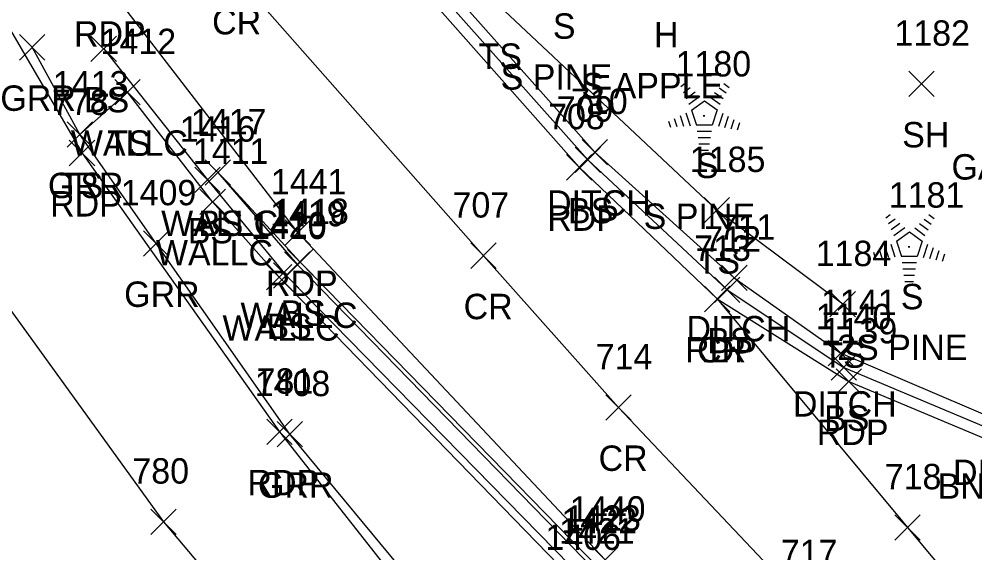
# Model space of a CAD drawing. Extents: x 1647133 to 1649138, y 411736 to 414924.
# Drawn here: x 1648689 to 1648764.3, y 412065.9 to 412107.9 of the extents above; entities that cross this region are included whole.
import ezdxf

# ---------------------------------------------------------------- set-up
doc = ezdxf.new("R2010")
doc.units = 0
for name, color, linetype in [('D_A', 7, 'Continuous'), ('D_I', 7, 'Continuous'), ('D_TIC', 7, 'Continuous'), ('DD', 7, 'Continuous'), ('L_A', 7, 'Continuous'), ('L_C', 7, 'Continuous'), ('L_I', 7, 'Continuous'), ('L_TIC', 7, 'Continuous'), ('LELB', 7, 'Continuous'), ('LTC', 7, 'Continuous'), ('LW', 7, 'Continuous'), ('M_C', 7, 'Continuous'), ('P_A', 7, 'Continuous'), ('P_I', 7, 'Continuous'), ('P_TIC', 7, 'Continuous'), ('PET', 7, 'Continuous'), ('PRC', 7, 'Continuous'), ('R_A', 7, 'Continuous'), ('R_C', 7, 'Continuous'), ('R_I', 7, 'Continuous'), ('R_TIC', 7, 'Continuous'), ('RGR', 7, 'Continuous')]:
    doc.layers.add(name, color=color, linetype=linetype)

msp = doc.modelspace()

# ---------------------------------------------------------------- linework, layer by layer
at = {"layer": 'D_TIC'}
for points in [[(1648733.341, 412096.427), (1648735.341, 412098.427)], [(1648735.341, 412096.427), (1648733.341, 412098.427)], [(1648744.316, 412086.535), (1648746.316, 412088.535)], [(1648746.316, 412086.535), (1648744.316, 412088.535)], [(1648752.692, 412080.611), (1648754.692, 412082.611)], [(1648754.692, 412080.611), (1648752.692, 412082.611)]]:
    msp.add_lwpolyline(points, dxfattribs=at)
at = {"layer": 'DD'}
msp.add_lwpolyline([(1648700.204, 412133.762), (1648700.854, 412134.053), (1648701.48, 412134.614), (1648714.403, 412119.84), (1648734.341, 412097.427), (1648745.316, 412087.535), (1648753.692, 412081.611), (1648766.293, 412076.231), (1648779.329, 412074.391), (1648786.441, 412074.562), (1648790.942, 412077.169), (1648801.739, 412083.078)], dxfattribs=at)
at = {"layer": 'L_TIC'}
for points in [[(1648694.678, 412104.565), (1648696.678, 412106.565)], [(1648696.678, 412104.565), (1648694.678, 412106.565)], [(1648759.039, 412101.804), (1648761.039, 412103.804)], [(1648761.039, 412101.804), (1648759.039, 412103.804)], [(1648696.556, 412101.144), (1648698.556, 412103.144)], [(1648698.556, 412101.144), (1648696.556, 412103.144)], [(1648696.556, 412101.144), (1648698.556, 412103.144)], [(1648698.556, 412101.144), (1648696.556, 412103.144)], [(1648692.801, 412097.81), (1648694.801, 412099.81)], [(1648694.801, 412097.81), (1648692.801, 412099.81)], [(1648732.781, 412095.829), (1648734.781, 412097.829)], [(1648734.781, 412095.829), (1648732.781, 412097.829)], [(1648702.852, 412094.255), (1648704.852, 412096.255)], [(1648704.852, 412094.255), (1648702.852, 412096.255)], [(1648703.664, 412094.833), (1648705.664, 412096.833)], [(1648705.664, 412094.833), (1648703.664, 412096.833)], [(1648703.664, 412094.833), (1648705.664, 412096.833)], [(1648705.664, 412094.833), (1648703.664, 412096.833)], [(1648703.253, 412092.509), (1648705.253, 412094.509)], [(1648705.253, 412092.509), (1648703.253, 412094.509)], [(1648742.94, 412091.867), (1648744.94, 412093.867)], [(1648744.94, 412091.867), (1648742.94, 412093.867)], [(1648709.908, 412087.591), (1648711.908, 412089.591)], [(1648711.908, 412087.591), (1648709.908, 412089.591)], [(1648710.149, 412087.766), (1648712.149, 412089.766)], [(1648712.149, 412087.766), (1648710.149, 412089.766)], [(1648708.494, 412086.59), (1648710.494, 412088.59)], [(1648710.494, 412086.59), (1648708.494, 412088.59)], [(1648709.046, 412086.718), (1648711.046, 412088.718)], [(1648711.046, 412086.718), (1648709.046, 412088.718)], [(1648743.747, 412085.599), (1648745.747, 412087.599)], [(1648745.747, 412085.599), (1648743.747, 412087.599)], [(1648752.845, 412084.455), (1648754.845, 412086.455)], [(1648754.845, 412084.455), (1648752.845, 412086.455)], [(1648752.939, 412079.489), (1648754.939, 412081.489)], [(1648754.939, 412079.489), (1648752.939, 412081.489)]]:
    msp.add_lwpolyline(points, dxfattribs=at)
at = {"layer": 'LELB'}
for points in [[(1648700.854, 412134.053), (1648713.799, 412119.311), (1648733.781, 412096.829), (1648744.747, 412086.599), (1648753.939, 412080.489), (1648766.731, 412075.085), (1648779.502, 412073.38), (1648786.989, 412073.92), (1648803.001, 412081.585)], [(1648753.845, 412085.455), (1648743.94, 412092.867), (1648726.772, 412108.987), (1648717.56, 412121.346)], [(1648695.678, 412105.565), (1648703.852, 412095.255), (1648710.046, 412087.718), (1648733.652, 412063.604), (1648760.182, 412036.756), (1648786.341, 412009.779), (1648811.728, 411984.211), (1648827.527, 411968.324), (1648831.218, 411963.386)], [(1648697.556, 412102.144), (1648693.801, 412098.81)], [(1648704.664, 412095.833), (1648711.149, 412088.766), (1648734.698, 412064.622), (1648761.086, 412037.999), (1648787.653, 412010.792), (1648812.355, 411985.321), (1648827.903, 411969.607)]]:
    msp.add_lwpolyline(points, dxfattribs=at)
at = {"layer": 'LTC'}
for p, q in [((1648741.099, 412102.595), (1648741.453, 412102.853)), ((1648741.308, 412102.13), (1648741.837, 412102.514)), ((1648741.518, 412101.664), (1648742.222, 412102.175)), ((1648743.755, 412102.139), (1648744.434, 412101.645)), ((1648744.126, 412102.487), (1648744.675, 412102.088)), ((1648744.497, 412102.836), (1648744.916, 412102.531)), ((1648741.727, 412101.198), (1648742.606, 412101.836)), ((1648741.952, 412100.743), (1648742.964, 412101.478)), ((1648742.964, 412101.478), (1648743.961, 412100.753)), ((1648743.384, 412101.791), (1648744.193, 412101.202)), ((1648741.952, 412100.743), (1648742.339, 412099.55)), ((1648743.961, 412100.753), (1648743.569, 412099.55)), ((1648740.131, 412099.874), (1648740.283, 412099.407)), ((1648740.587, 412100.091), (1648740.798, 412099.439)), ((1648741.042, 412100.308), (1648741.313, 412099.472)), ((1648741.497, 412100.524), (1648741.828, 412099.505)), ((1648744.398, 412100.482), (1648744.06, 412099.442)), ((1648744.843, 412100.232), (1648744.555, 412099.347)), ((1648745.287, 412099.982), (1648745.05, 412099.252)), ((1648743.569, 412099.55), (1648742.339, 412099.55)), ((1648745.732, 412099.731), (1648745.545, 412099.157)), ((1648743.531, 412099.05), (1648742.387, 412099.05)), ((1648743.447, 412098.55), (1648742.459, 412098.55)), ((1648743.364, 412098.05), (1648742.532, 412098.05)), ((1648743.28, 412097.55), (1648742.605, 412097.55)), ((1648757.229, 412092.27), (1648757.583, 412092.527)), ((1648760.627, 412092.51), (1648761.046, 412092.206)), ((1648757.438, 412091.805), (1648757.968, 412092.189)), ((1648757.648, 412091.339), (1648758.352, 412091.85)), ((1648759.885, 412091.814), (1648760.564, 412091.32)), ((1648760.256, 412092.162), (1648760.806, 412091.763)), ((1648757.858, 412090.873), (1648758.736, 412091.511)), ((1648758.082, 412090.418), (1648759.094, 412091.152)), ((1648759.094, 412091.152), (1648760.091, 412090.428)), ((1648759.514, 412091.465), (1648760.323, 412090.877)), ((1648757.628, 412090.199), (1648757.958, 412089.18)), ((1648758.082, 412090.418), (1648758.469, 412089.225)), ((1648760.091, 412090.428), (1648759.7, 412089.225)), ((1648760.528, 412090.157), (1648760.191, 412089.117)), ((1648756.261, 412089.549), (1648756.413, 412089.081)), ((1648756.717, 412089.766), (1648756.928, 412089.114)), ((1648757.172, 412089.983), (1648757.443, 412089.147)), ((1648760.973, 412089.906), (1648760.686, 412089.022)), ((1648761.418, 412089.656), (1648761.181, 412088.927)), ((1648761.862, 412089.406), (1648761.675, 412088.832)), ((1648759.7, 412089.225), (1648758.469, 412089.225)), ((1648759.661, 412088.725), (1648758.517, 412088.725)), ((1648759.578, 412088.225), (1648758.589, 412088.225)), ((1648759.494, 412087.725), (1648758.662, 412087.725)), ((1648759.41, 412087.225), (1648758.735, 412087.225))]:
    msp.add_line(p, q, dxfattribs=at)
at = {"layer": 'LW'}
for points in [[(1648830.392, 411963.284), (1648792.891, 412001.948), (1648759.271, 412036.695), (1648733.27, 412063.116), (1648709.494, 412087.59), (1648704.253, 412093.509), (1648697.556, 412102.144)], [(1648704.664, 412095.833), (1648710.908, 412088.591), (1648734.403, 412064.434), (1648760.897, 412037.563), (1648787.2, 412010.572), (1648812.273, 411985.189), (1648827.903, 411969.607)]]:
    msp.add_lwpolyline(points, dxfattribs=at)
at = {"layer": 'P_TIC'}
for points in [[(1648692.972, 412096.362), (1648694.972, 412098.362)], [(1648694.972, 412096.362), (1648692.972, 412098.362)], [(1648732.101, 412095.235), (1648734.101, 412097.235)], [(1648734.101, 412095.235), (1648732.101, 412097.235)], [(1648709.962, 412090.103), (1648711.962, 412092.103)], [(1648711.962, 412090.103), (1648709.962, 412092.103)], [(1648724.575, 412088.279), (1648726.575, 412090.279)], [(1648726.575, 412088.279), (1648724.575, 412090.279)], [(1648742.955, 412084.872), (1648744.955, 412086.872)], [(1648744.955, 412084.872), (1648742.955, 412086.872)], [(1648742.955, 412084.872), (1648744.955, 412086.872)], [(1648744.955, 412084.872), (1648742.955, 412086.872)], [(1648753.321, 412078.376), (1648755.321, 412080.376)], [(1648755.321, 412078.376), (1648753.321, 412080.376)], [(1648735.199, 412076.337), (1648737.199, 412078.337)], [(1648737.199, 412076.337), (1648735.199, 412078.337)], [(1648708.507, 412074.411), (1648710.507, 412076.411)], [(1648710.507, 412074.411), (1648708.507, 412076.411)], [(1648699.383, 412067.335), (1648701.383, 412069.335)], [(1648701.383, 412067.335), (1648699.383, 412069.335)], [(1648757.948, 412066.89), (1648759.948, 412068.89)], [(1648759.948, 412066.89), (1648757.948, 412068.89)], [(1648734.153, 412064.343), (1648736.153, 412066.343)], [(1648736.153, 412064.343), (1648734.153, 412066.343)]]:
    msp.add_lwpolyline(points, dxfattribs=at)
at = {"layer": 'PET'}
for points in [[(1648536.119, 412432.998), (1648543.399, 412417.954), (1648546.486, 412415.003), (1648562.248, 412380.849), (1648562.337, 412375.739), (1648565.289, 412369.171), (1648579.297, 412340.19), (1648594.414, 412306.778), (1648606.351, 412280.635), (1648620.629, 412249.259), (1648631.777, 412225.06), (1648641.267, 412204.566), (1648646.814, 412192.55), (1648664.816, 412155.812), (1648677.431, 412126.914), (1648681.854, 412118.139), (1648693.972, 412097.362), (1648709.507, 412075.411), (1648723.887, 412057.125), (1648746.982, 412031.15), (1648768.696, 412011.078), (1648794.521, 411987.621), (1648826.406, 411959.789)], [(1648646.814, 412192.55), (1648654.671, 412182.929), (1648666.114, 412172.04), (1648681.295, 412155.026), (1648700.204, 412133.762), (1648713.219, 412118.744), (1648733.101, 412096.235), (1648743.955, 412085.872), (1648754.321, 412079.376), (1648767.034, 412074.054), (1648779.661, 412072.471), (1648787.719, 412072.973), (1648803.342, 412081.153)], [(1648833.709, 411965.976), (1648813.189, 411986.13), (1648788.104, 412011.597), (1648761.506, 412038.635), (1648735.153, 412065.343), (1648710.962, 412091.103), (1648695.849, 412110.74)]]:
    msp.add_lwpolyline(points, dxfattribs=at)
at = {"layer": 'PRC'}
for points in [[(1648523.855, 412428.164), (1648541.762, 412388.819), (1648560.786, 412347.218), (1648578.952, 412307.656), (1648596.522, 412268.849), (1648615.514, 412228.06), (1648629.383, 412198.525), (1648645.407, 412164.541), (1648659.578, 412134.14), (1648672.041, 412110.748), (1648683.898, 412091.11), (1648700.383, 412068.335), (1648715.839, 412049.98), (1648739.601, 412024.905), (1648761.868, 412004.355), (1648787.636, 411981.064), (1648820.993, 411950.624), (1648837.381, 411936.249), (1648865.129, 411910.894), (1648893.845, 411885.618), (1648930.35, 411852.903), (1648951.421, 411834.103), (1648988.1, 411800.425), (1649025.041, 411766.663)], [(1648664.816, 412155.812), (1648676.979, 412144.697), (1648692.804, 412127.015), (1648705.779, 412111.7), (1648725.575, 412089.279), (1648736.199, 412077.337), (1648750.767, 412061.914), (1648770.244, 412040.325), (1648787.372, 412023.03), (1648802.926, 412006.988), (1648820.913, 411988.588), (1648839.835, 411968.01), (1648856.098, 411949.207), (1648864.815, 411933.931), (1648873.225, 411921.132)], [(1648743.955, 412085.872), (1648758.948, 412067.89), (1648776.375, 412047.027), (1648792.583, 412027.973)]]:
    msp.add_lwpolyline(points, dxfattribs=at)
at = {"layer": 'R_TIC'}
for points in [[(1648689.054, 412104.682), (1648691.054, 412106.682)], [(1648691.054, 412104.682), (1648689.054, 412106.682)], [(1648692.801, 412097.81), (1648694.801, 412099.81)], [(1648694.801, 412097.81), (1648692.801, 412099.81)], [(1648698.799, 412089.248), (1648700.799, 412091.248)], [(1648700.799, 412089.248), (1648698.799, 412091.248)], [(1648709.333, 412074.22), (1648711.333, 412076.22)], [(1648711.333, 412074.22), (1648709.333, 412076.22)]]:
    msp.add_lwpolyline(points, dxfattribs=at)
at = {"layer": 'RGR'}
msp.add_lwpolyline([(1648828.248, 411959.455), (1648783.912, 411998.445), (1648752.672, 412027.834), (1648730.332, 412051.085), (1648710.333, 412075.22), (1648699.799, 412090.248), (1648693.801, 412098.81), (1648690.054, 412105.682)], dxfattribs=at)

# ---------------------------------------------------------------- texts
at = {"layer": 'D_A'}
for p in [(1648730.577, 412092.427), (1648741.552, 412082.535), (1648749.928, 412076.611), (1648762.529, 412071.231)]:
    msp.add_text('DITCH', height=2, dxfattribs=at).set_placement(p)
at = {"layer": 'D_I'}
for s, p in [('710', (1648732.459, 412100.427)), ('711', (1648744.087, 412090.535)), ('1141', (1648752.133, 412084.611))]:
    msp.add_text(s, height=2, dxfattribs=at).set_placement(p)
at = {"layer": 'L_A'}
for s, p in [('S', (1648731.032, 412106.356)), ('H', (1648738.99, 412105.672)), ('TS', (1648725.181, 412103.987)), ('BS', (1648694.119, 412100.565)), ('WALLC', (1648693.091, 412097.144)), ('TS', (1648695.965, 412097.144)), ('SH', (1648758.527, 412097.804)), ('S', (1648742.289, 412095.387)), ('TS', (1648692.211, 412093.81)), ('BS', (1648732.222, 412091.829)), ('WALLC', (1648700.199, 412090.833)), ('BS', (1648703.105, 412090.833)), ('BS', (1648702.293, 412090.255)), ('WALLC', (1648699.789, 412088.509)), ('TS', (1648742.349, 412087.867)), ('S', (1648758.42, 412085.062)), ('WALLC', (1648706.443, 412083.591)), ('BS', (1648709.59, 412083.766)), ('WALLC', (1648705.029, 412082.59)), ('BS', (1648708.487, 412082.718)), ('BS', (1648743.188, 412081.599)), ('TS', (1648752.254, 412080.455)), ('BS', (1648752.38, 412075.489))]:
    msp.add_text(s, height=2, dxfattribs=at).set_placement(p)
at = {"layer": 'L_C'}
for s, p in [('S PINE', (1648726.922, 412102.356)), ('S APPLE', (1648733.29, 412101.672)), ('S PINE', (1648738.179, 412091.387)), ('2S PINE', (1648753.412, 412081.062))]:
    msp.add_text(s, height=2, dxfattribs=at).set_placement(p)
at = {"layer": 'L_I'}
for s, p in [('1182', (1648757.913, 412105.804)), ('1412', (1648695.43, 412105.144)), ('1412', (1648695.43, 412105.144)), ('1180', (1648740.691, 412103.387)), ('1413', (1648691.675, 412101.81)), ('709', (1648731.333, 412099.829)), ('1417', (1648702.538, 412098.833)), ('1417', (1648702.538, 412098.833)), ('1416', (1648701.671, 412098.255)), ('1411', (1648702.694, 412096.509)), ('1185', (1648741.814, 412095.867)), ('1181', (1648757.475, 412093.062)), ('1419', (1648708.774, 412091.591)), ('1418', (1648709.023, 412091.766)), ('1420', (1648707.267, 412090.718)), ('1410', (1648707.281, 412090.59)), ('712', (1648742.952, 412089.599)), ('1184', (1648751.719, 412088.455)), ('1140', (1648751.726, 412083.489)), ('1422', (1648731.711, 412067.434)), ('1423', (1648732.005, 412067.622)), ('1421', (1648731.526, 412066.604)), ('1406', (1648730.444, 412066.116))]:
    msp.add_text(s, height=2, dxfattribs=at).set_placement(p)
at = {"layer": 'LTC'}
for p in [(1648742.846, 412100.491), (1648758.976, 412090.166)]:
    msp.add_text('.', height=1.037, rotation=270, dxfattribs=at).set_placement(p)
at = {"layer": 'M_C'}
msp.add_text('BND IS CVPS PROPERTY CORNER', height=2, dxfattribs=at).set_placement((1648761.316, 412070.145))
at = {"layer": 'P_A'}
for s, p in [('CR', (1648704.212, 412106.7)), ('RDP', (1648693.337, 412105.74)), ('RDP', (1648693.337, 412105.74)), ('RDP', (1648691.461, 412092.362)), ('RDP', (1648730.589, 412091.235)), ('RDP', (1648708.45, 412086.103)), ('CR', (1648724.008, 412084.279)), ('RDP', (1648741.443, 412080.872)), ('CR', (1648742.388, 412080.872)), ('RDP', (1648751.809, 412074.376)), ('CR', (1648734.632, 412072.337)), ('RDP', (1648706.995, 412070.411))]:
    msp.add_text(s, height=2, dxfattribs=at).set_placement(p)
at = {"layer": 'P_I'}
for s, p in [('778', (1648691.61, 412100.362)), ('708', (1648730.66, 412099.235)), ('1441', (1648708.836, 412094.103)), ('707', (1648723.134, 412092.279)), ('713', (1648742.159, 412088.872)), ('713', (1648742.159, 412088.872)), ('1139', (1648752.187, 412082.376)), ('714', (1648734.404, 412080.337)), ('781', (1648707.712, 412078.411)), ('780', (1648697.934, 412071.335)), ('718', (1648757.153, 412070.89)), ('1440', (1648732.373, 412068.343)), ('717', (1648748.972, 412064.914))]:
    msp.add_text(s, height=2, dxfattribs=at).set_placement(p)
at = {"layer": 'R_A'}
for p in [(1648687.542, 412100.682), (1648691.29, 412093.81), (1648697.287, 412085.248), (1648707.822, 412070.22)]:
    msp.add_text('GRR', height=2, dxfattribs=at).set_placement(p)
at = {"layer": 'R_C'}
msp.add_text('GATE POST', height=2, dxfattribs=at).set_placement((1648762.41, 412095.27))
at = {"layer": 'R_I'}
for s, p in [('1413', (1648691.675, 412101.81)), ('1409', (1648697.019, 412093.248)), ('1408', (1648707.562, 412078.22))]:
    msp.add_text(s, height=2, dxfattribs=at).set_placement(p)

doc.saveas('drawing.dxf')
